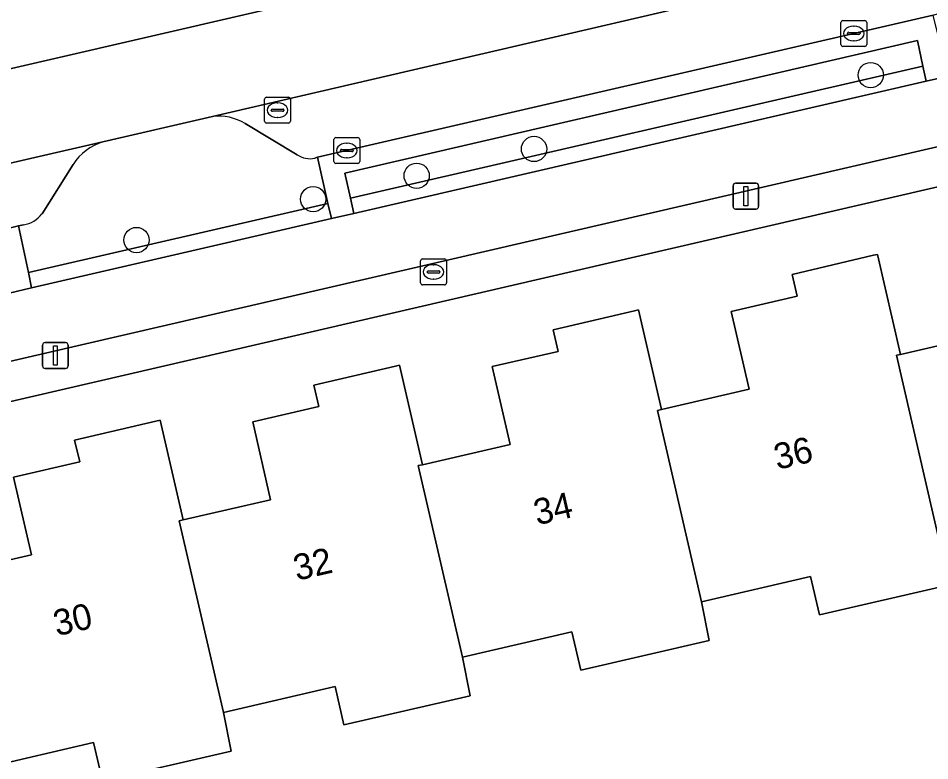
# Model space of a CAD drawing. Extents: x 156412 to 157779, y 382335 to 383768.
# Drawn here: x 156851.95 to 156887.22, y 382924.67 to 382953.4 of the extents above; entities that cross this region are included whole.
import ezdxf

# ---------------------------------------------------------------- set-up
doc = ezdxf.new("R2010")
doc.units = 0
for name, color, linetype in [('IMGEO_Berm_groen', 7, 'Continuous'), ('IMGEO_Boom', 7, 'Continuous'), ('IMGEO_Brandkraan', 7, 'Continuous'), ('IMGEO_Erf', 7, 'Continuous'), ('IMGEO_Fietspad_gesloten', 7, 'Continuous'), ('IMGEO_Groenvoorziening', 7, 'Continuous'), ('IMGEO_Haag', 7, 'Continuous'), ('IMGEO_Kolk', 7, 'Continuous'), ('IMGEO_Lichtmast', 7, 'Continuous'), ('IMGEO_Pand', 7, 'Continuous'), ('IMGEO_Pand_nummerreeks', 7, 'Continuous'), ('IMGEO_Parkeervlak_open', 7, 'Continuous'), ('IMGEO_Rijbaan_regionaal_gesloten', 7, 'Continuous'), ('IMGEO_Rioolput', 7, 'Continuous'), ('IMGEO_Voetpad_open', 7, 'Continuous')]:
    doc.layers.add(name, color=color, linetype=linetype)

msp = doc.modelspace()

# ---------------------------------------------------------------- linework, layer by layer
at = {"layer": 'IMGEO_Berm_groen'}
msp.add_lwpolyline([(156886.962, 382951.547), (156886.748, 382952.533), (156864.584, 382947.403), (156864.803, 382946.432)], close=True, dxfattribs=at)
for points in [[(156859.463, 382949.6), (156855.226, 382948.615)], [(156862.74, 382948.115), (156860.735, 382949.326)], [(156852.15, 382945.404), (156851.962, 382945.371), (156852.339, 382943.555), (156863.935, 382946.232), (156863.529, 382948.017)], [(156854.068, 382947.742), (156852.867, 382945.83)], [(156863.529, 382948.017), (156863.421, 382947.98)]]:
    msp.add_lwpolyline(points, dxfattribs=at)
for centre, radius, start, end in [((156859.679, 382947.512), 2.099, 59.7879, 95.8996), ((156855.857, 382946.574), 2.137, 107.174, 146.8503), ((156863.237, 382948.836), 0.875, 235.421, 282.1534), ((156851.957, 382946.545), 1.157, 279.5863, 321.8464)]:
    msp.add_arc(centre, radius, start, end, dxfattribs=at)
at = {"layer": 'IMGEO_Boom'}
for centre in [(156884.939, 382951.198), (156871.909, 382948.34), (156867.367, 382947.304), (156863.362, 382946.399), (156856.524, 382944.817)]:
    msp.add_circle(centre, 0.489, dxfattribs=at)
at = {"layer": 'IMGEO_Brandkraan'}
for p, q in [((156867.52, 382943.158), (156867.52, 382944.01)), ((156867.595, 382944.084), (156868.447, 382944.084)), ((156868.008, 382943.864), (156868.033, 382943.864)), ((156868.521, 382944.01), (156868.521, 382943.158)), ((156867.779, 382943.578), (156867.779, 382943.59)), ((156868.217, 382943.541), (156867.819, 382943.541)), ((156867.822, 382943.627), (156868.22, 382943.627)), ((156868.263, 382943.59), (156868.263, 382943.578)), ((156868.031, 382943.304), (156868.006, 382943.304)), ((156868.447, 382943.084), (156867.595, 382943.084))]:
    msp.add_line(p, q, dxfattribs=at)
for points in [[(156867.52, 382943.158), (156867.52, 382944.01)], [(156867.595, 382944.084), (156868.447, 382944.084)], [(156868.521, 382944.01), (156868.521, 382943.158)], [(156868.447, 382943.084), (156867.595, 382943.084)]]:
    msp.add_lwpolyline(points, dxfattribs=at)
for centre, radius, start, end in [((156867.597, 382944.008), 0.0765, 91.552, 178.448), ((156867.597, 382944.008), 0.0765, 91.552, 178.448), ((156868.445, 382944.008), 0.0765, 1.552, 88.448), ((156868.445, 382944.008), 0.0765, 1.552, 88.448), ((156867.819, 382943.587), 0.0403, 85.8775, 175.7526), ((156867.816, 382943.577), 0.0366, 178.938, 274.7102), ((156868.22, 382943.584), 0.043, 264.8664, 352.4533), ((156868.224, 382943.589), 0.0386, 1.7309, 96.639), ((156867.597, 382943.16), 0.0765, 181.552, 268.448), ((156867.597, 382943.16), 0.0765, 181.552, 268.448), ((156868.445, 382943.16), 0.0765, 271.552, 358.448), ((156868.445, 382943.16), 0.0765, 271.552, 358.448)]:
    msp.add_arc(centre, radius, start, end, dxfattribs=at)
for centre, major_axis, ratio, start_param, end_param in [((156868.007, 382943.584), (-0.387, 0.002), 0.722429, 4.712389, 7.853982), ((156868.032, 382943.584), (-0.39, 0.002), 0.717154, 1.570796, 4.712389)]:
    msp.add_ellipse(centre, major_axis=major_axis, ratio=ratio, start_param=start_param, end_param=end_param, dxfattribs=at)
at = {"layer": 'IMGEO_Erf'}
for points in [[(156903.296, 382950.523), (156828.922, 382933.312)], [(156849.094, 382931.86), (156852.463, 382932.637), (156851.769, 382935.646), (156854.325, 382936.236), (156854.131, 382937.073), (156857.276, 382937.806), (156857.442, 382937.845), (156858.331, 382933.991), (156861.707, 382934.77), (156861.023, 382937.781), (156863.582, 382938.372), (156863.389, 382939.207), (156866.542, 382939.942), (156866.699, 382939.979), (156867.588, 382936.126), (156870.985, 382936.91), (156870.291, 382939.92), (156872.847, 382940.51), (156872.655, 382941.344), (156875.797, 382942.083), (156875.952, 382942.119), (156876.842, 382938.261), (156880.23, 382939.043), (156879.535, 382942.053), (156882.092, 382942.643), (156881.898, 382943.484), (156885.05, 382944.228), (156885.198, 382944.263), (156886.09, 382940.395), (156889.48, 382941.177)], [(156887.931, 382931.468), (156882.956, 382930.318), (156882.614, 382931.798), (156878.388, 382930.821), (156878.691, 382929.332), (156873.716, 382928.181), (156873.374, 382929.661), (156869.138, 382928.681), (156869.432, 382927.191), (156864.554, 382926.063), (156864.212, 382927.542), (156859.889, 382926.543), (156860.182, 382925.052), (156855.207, 382923.901), (156854.865, 382925.381), (156850.649, 382924.406)]]:
    msp.add_lwpolyline(points, dxfattribs=at)
at = {"layer": 'IMGEO_Fietspad_gesloten'}
msp.add_lwpolyline([(156674.773, 382899.258), (156767.182, 382920.602), (156826.292, 382934.262), (156902.955, 382951.999), (156911.251, 382953.909), (156913.318, 382954.385), (156939.803, 382960.484), (156939.156, 382962.984), (156887.943, 382951.159), (156887.089, 382950.962), (156864.935, 382945.847), (156864.068, 382945.647), (156859.834, 382944.669), (156852.462, 382942.964), (156851.598, 382942.764), (156830.312, 382937.841), (156829.479, 382937.648), (156815.976, 382934.507), (156815.173, 382934.345)], dxfattribs=at)
at = {"layer": 'IMGEO_Groenvoorziening'}
for points in [[(156887.089, 382950.962), (156886.962, 382951.547), (156864.803, 382946.432), (156864.935, 382945.847)], [(156859.834, 382944.669), (156864.068, 382945.647), (156863.935, 382946.232), (156852.339, 382943.555), (156852.462, 382942.964)]]:
    msp.add_lwpolyline(points, close=True, dxfattribs=at)
at = {"layer": 'IMGEO_Haag'}
for points in [[(156886.962, 382951.547), (156864.803, 382946.432), (156864.935, 382945.847), (156887.089, 382950.962)], [(156863.935, 382946.232), (156852.339, 382943.555), (156852.462, 382942.964), (156859.834, 382944.669), (156864.068, 382945.647)]]:
    msp.add_lwpolyline(points, close=True, dxfattribs=at)
at = {"layer": 'IMGEO_Kolk'}
for p, q in [((156883.784, 382952.382), (156883.784, 382953.234)), ((156883.859, 382953.308), (156884.711, 382953.308)), ((156884.272, 382953.088), (156884.297, 382953.088)), ((156884.785, 382953.234), (156884.785, 382952.382)), ((156884.043, 382952.802), (156884.043, 382952.814)), ((156884.481, 382952.765), (156884.083, 382952.765)), ((156884.086, 382952.851), (156884.484, 382952.851)), ((156884.527, 382952.814), (156884.527, 382952.802)), ((156884.711, 382952.308), (156883.859, 382952.308)), ((156884.295, 382952.528), (156884.27, 382952.528)), ((156864.24, 382948.779), (156865.092, 382948.779)), ((156864.165, 382947.853), (156864.165, 382948.705)), ((156864.653, 382948.559), (156864.678, 382948.559)), ((156865.166, 382948.705), (156865.166, 382947.853)), ((156864.424, 382948.273), (156864.424, 382948.285)), ((156864.862, 382948.236), (156864.464, 382948.236)), ((156864.467, 382948.322), (156864.865, 382948.322)), ((156864.908, 382948.285), (156864.908, 382948.273)), ((156865.092, 382947.779), (156864.24, 382947.779)), ((156864.676, 382947.999), (156864.651, 382947.999))]:
    msp.add_line(p, q, dxfattribs=at)
for points in [[(156883.784, 382952.382), (156883.784, 382953.234)], [(156883.859, 382953.308), (156884.711, 382953.308)], [(156884.785, 382953.234), (156884.785, 382952.382)], [(156884.711, 382952.308), (156883.859, 382952.308)], [(156864.24, 382948.779), (156865.092, 382948.779)], [(156864.165, 382947.853), (156864.165, 382948.705)], [(156865.166, 382948.705), (156865.166, 382947.853)], [(156865.092, 382947.779), (156864.24, 382947.779)]]:
    msp.add_lwpolyline(points, dxfattribs=at)
for centre, radius, start, end in [((156883.861, 382953.232), 0.0765, 91.552, 178.448), ((156883.861, 382953.232), 0.0765, 91.552, 178.448), ((156884.709, 382953.232), 0.0765, 1.552, 88.448), ((156884.709, 382953.232), 0.0765, 1.552, 88.448), ((156884.083, 382952.811), 0.0403, 85.8775, 175.7526), ((156884.08, 382952.801), 0.0366, 178.938, 274.7102), ((156884.484, 382952.808), 0.043, 264.8664, 352.4533), ((156884.488, 382952.813), 0.0386, 1.7309, 96.639), ((156883.861, 382952.384), 0.0765, 181.552, 268.448), ((156883.861, 382952.384), 0.0765, 181.552, 268.448), ((156884.709, 382952.384), 0.0765, 271.552, 358.448), ((156884.709, 382952.384), 0.0765, 271.552, 358.448), ((156864.242, 382948.703), 0.0765, 91.552, 178.448), ((156864.242, 382948.703), 0.0765, 91.552, 178.448), ((156865.09, 382948.703), 0.0765, 1.552, 88.448), ((156865.09, 382948.703), 0.0765, 1.552, 88.448), ((156864.464, 382948.282), 0.0403, 85.8775, 175.7526), ((156864.461, 382948.272), 0.0366, 178.938, 274.7102), ((156864.865, 382948.279), 0.043, 264.8664, 352.4533), ((156864.869, 382948.284), 0.0386, 1.7309, 96.639), ((156864.242, 382947.855), 0.0765, 181.552, 268.448), ((156864.242, 382947.855), 0.0765, 181.552, 268.448), ((156865.09, 382947.855), 0.0765, 271.552, 358.448), ((156865.09, 382947.855), 0.0765, 271.552, 358.448)]:
    msp.add_arc(centre, radius, start, end, dxfattribs=at)
for centre, major_axis, ratio, start_param, end_param in [((156884.271, 382952.808), (-0.387, 0.002), 0.722429, 4.712389, 7.853982), ((156884.296, 382952.808), (-0.39, 0.002), 0.717154, 1.570796, 4.712389), ((156864.652, 382948.279), (-0.387, 0.002), 0.722429, 4.712389, 7.853982), ((156864.677, 382948.279), (-0.39, 0.002), 0.717154, 1.570796, 4.712389)]:
    msp.add_ellipse(centre, major_axis=major_axis, ratio=ratio, start_param=start_param, end_param=end_param, dxfattribs=at)
at = {"layer": 'IMGEO_Lichtmast'}
for p, q in [((156879.71, 382947.017), (156880.5, 382947.017)), ((156880.5, 382947.017), (156879.71, 382947.017)), ((156879.61, 382946.117), (156879.61, 382946.917)), ((156879.61, 382946.917), (156879.61, 382946.117)), ((156880.6, 382946.917), (156880.6, 382946.117)), ((156880.6, 382946.117), (156880.6, 382946.917)), ((156880.5, 382946.017), (156879.71, 382946.017)), ((156879.71, 382946.017), (156880.5, 382946.017)), ((156852.889, 382939.95), (156852.889, 382940.75)), ((156852.889, 382940.75), (156852.889, 382939.95)), ((156852.989, 382940.85), (156853.779, 382940.85)), ((156853.779, 382940.85), (156852.989, 382940.85)), ((156853.879, 382940.75), (156853.879, 382939.95)), ((156853.879, 382939.95), (156853.879, 382940.75)), ((156853.779, 382939.85), (156852.989, 382939.85)), ((156852.989, 382939.85), (156853.779, 382939.85))]:
    msp.add_line(p, q, dxfattribs=at)
for points in [[(156880.03, 382946.892), (156880.18, 382946.892), (156880.18, 382946.142), (156880.03, 382946.142), (156880.03, 382946.892)], [(156853.309, 382940.725), (156853.459, 382940.725), (156853.459, 382939.975), (156853.309, 382939.975), (156853.309, 382940.725)]]:
    msp.add_lwpolyline(points, dxfattribs=at)
for centre, start, end in [((156879.71, 382946.917), 90, 180), ((156879.71, 382946.917), 90, 180), ((156880.5, 382946.917), 0, 90), ((156880.5, 382946.917), 360, 90), ((156879.71, 382946.117), 180, 270), ((156879.71, 382946.117), 180, 270), ((156880.5, 382946.117), 270, 0), ((156880.5, 382946.117), 270, 0), ((156852.989, 382940.75), 90, 180), ((156852.989, 382940.75), 90, 180), ((156853.779, 382940.75), 0, 90), ((156853.779, 382940.75), 360, 90), ((156852.989, 382939.95), 180, 270), ((156852.989, 382939.95), 180, 270), ((156853.779, 382939.95), 270, 0), ((156853.779, 382939.95), 270, 0)]:
    msp.add_arc(centre, 0.1, start, end, dxfattribs=at)
at = {"layer": 'IMGEO_Pand'}
for points in [[(156895.379, 382942.538), (156894.488, 382946.399), (156894.308, 382946.357), (156891.153, 382945.628), (156891.349, 382944.779), (156888.785, 382944.187), (156889.48, 382941.177), (156886.09, 382940.395), (156885.938, 382940.36), (156887.638, 382932.959), (156891.863, 382933.937), (156892.205, 382932.457), (156897.19, 382933.61), (156896.897, 382935.101), (156895.196, 382942.496)], [(156876.842, 382938.261), (156876.685, 382938.225), (156878.388, 382930.821), (156882.614, 382931.798), (156882.956, 382930.318), (156887.931, 382931.468), (156887.638, 382932.959), (156885.938, 382940.36), (156886.09, 382940.395), (156885.198, 382944.263), (156885.05, 382944.228), (156881.898, 382943.484), (156882.092, 382942.643), (156879.535, 382942.053), (156880.23, 382939.043)], [(156867.588, 382936.126), (156867.43, 382936.09), (156869.138, 382928.681), (156873.374, 382929.661), (156873.716, 382928.181), (156878.691, 382929.332), (156878.388, 382930.821), (156876.685, 382938.225), (156876.842, 382938.261), (156875.952, 382942.119), (156875.797, 382942.083), (156872.655, 382941.344), (156872.847, 382940.51), (156870.291, 382939.92), (156870.985, 382936.91)], [(156867.588, 382936.126), (156866.699, 382939.979), (156866.542, 382939.942), (156863.389, 382939.207), (156863.582, 382938.372), (156861.023, 382937.781), (156861.707, 382934.77), (156858.331, 382933.991), (156858.17, 382933.954), (156859.889, 382926.543), (156864.212, 382927.542), (156864.554, 382926.063), (156869.432, 382927.191), (156869.138, 382928.681), (156867.43, 382936.09)], [(156849.094, 382931.86), (156848.925, 382931.821), (156850.649, 382924.406), (156854.865, 382925.381), (156855.207, 382923.901), (156860.182, 382925.052), (156859.889, 382926.543), (156858.17, 382933.954), (156858.331, 382933.991), (156857.442, 382937.845), (156857.276, 382937.806), (156854.131, 382937.073), (156854.325, 382936.236), (156851.769, 382935.646), (156852.463, 382932.637)]]:
    msp.add_lwpolyline(points, close=True, dxfattribs=at)
at = {"layer": 'IMGEO_Parkeervlak_open'}
for points in [[(156890.458, 382956.801), (156859.463, 382949.6)], [(156863.421, 382947.98), (156863.529, 382948.017), (156887.359, 382953.518), (156887.565, 382953.583)], [(156860.735, 382949.326), (156862.74, 382948.115)], [(156855.226, 382948.615), (156824.808, 382941.614)], [(156852.867, 382945.83), (156854.068, 382947.742)], [(156828.775, 382940.011), (156828.946, 382940.054), (156845.143, 382943.683), (156851.962, 382945.371), (156852.15, 382945.404)]]:
    msp.add_lwpolyline(points, dxfattribs=at)
for centre, radius, start, end in [((156859.679, 382947.512), 2.099, 59.7879, 95.8996), ((156855.857, 382946.574), 2.137, 107.174, 146.8503), ((156863.237, 382948.836), 0.875, 235.421, 282.1534), ((156851.957, 382946.545), 1.157, 279.5863, 321.8464)]:
    msp.add_arc(centre, radius, start, end, dxfattribs=at)
at = {"layer": 'IMGEO_Rijbaan_regionaal_gesloten'}
msp.add_lwpolyline([(156816.196, 382943.116), (156816.29, 382943.135), (156830.232, 382946.499), (156903.004, 382963.32), (156939.797, 382971.848)], dxfattribs=at)
msp.add_lwpolyline([(156940.547, 382968.546), (156939.797, 382971.848), (156903.004, 382963.32), (156830.232, 382946.499), (156816.29, 382943.135), (156816.196, 382943.116), (156816.994, 382939.753), (156818.685, 382940.216), (156824.808, 382941.614), (156855.226, 382948.615), (156859.463, 382949.6), (156890.458, 382956.801), (156893.4, 382957.443), (156903.126, 382959.769)], close=True, dxfattribs=at)
at = {"layer": 'IMGEO_Rioolput'}
for p, q in [((156861.482, 382949.413), (156861.482, 382950.265)), ((156861.557, 382950.339), (156862.409, 382950.339)), ((156862.483, 382950.265), (156862.483, 382949.413)), ((156861.741, 382949.833), (156861.741, 382949.845)), ((156861.784, 382949.882), (156862.182, 382949.882)), ((156861.97, 382950.119), (156861.995, 382950.119)), ((156862.225, 382949.845), (156862.225, 382949.833)), ((156862.179, 382949.796), (156861.781, 382949.796)), ((156861.993, 382949.559), (156861.968, 382949.559)), ((156862.409, 382949.339), (156861.557, 382949.339))]:
    msp.add_line(p, q, dxfattribs=at)
for points in [[(156861.482, 382949.413), (156861.482, 382950.265)], [(156861.557, 382950.339), (156862.409, 382950.339)], [(156862.483, 382950.265), (156862.483, 382949.413)], [(156862.409, 382949.339), (156861.557, 382949.339)]]:
    msp.add_lwpolyline(points, dxfattribs=at)
for centre, radius, start, end in [((156861.559, 382950.263), 0.0765, 91.552, 178.448), ((156861.559, 382950.263), 0.0765, 91.552, 178.448), ((156862.407, 382950.263), 0.0765, 1.552, 88.448), ((156862.407, 382950.263), 0.0765, 1.552, 88.448), ((156861.781, 382949.842), 0.0403, 85.8775, 175.7526), ((156861.778, 382949.832), 0.0366, 178.938, 274.7102), ((156862.182, 382949.839), 0.043, 264.8664, 352.4533), ((156862.186, 382949.844), 0.0386, 1.7309, 96.639), ((156861.559, 382949.415), 0.0765, 181.552, 268.448), ((156861.559, 382949.415), 0.0765, 181.552, 268.448), ((156862.407, 382949.415), 0.0765, 271.552, 358.448), ((156862.407, 382949.415), 0.0765, 271.552, 358.448)]:
    msp.add_arc(centre, radius, start, end, dxfattribs=at)
for centre, major_axis, ratio, start_param, end_param in [((156861.969, 382949.839), (-0.387, 0.002), 0.722429, 4.712389, 7.853982), ((156861.994, 382949.839), (-0.39, 0.002), 0.717154, 1.570796, 4.712389)]:
    msp.add_ellipse(centre, major_axis=major_axis, ratio=ratio, start_param=start_param, end_param=end_param, dxfattribs=at)
at = {"layer": 'IMGEO_Voetpad_open'}
for points in [[(156903.296, 382950.523), (156904.698, 382950.847), (156910.458, 382952.176), (156911.592, 382952.432), (156911.251, 382953.909), (156902.955, 382951.999), (156826.292, 382934.262), (156767.182, 382920.602), (156674.773, 382899.258)], [(156673.213, 382897.345), (156682.265, 382899.418), (156684.12, 382899.829), (156774.309, 382920.694), (156774.651, 382920.773), (156774.992, 382920.852), (156776.018, 382921.089), (156779.301, 382921.834), (156780.385, 382922.087), (156781.069, 382922.247), (156806.375, 382928.091), (156824.938, 382932.403), (156827.589, 382932.999), (156827.978, 382933.083), (156828.922, 382933.312), (156903.296, 382950.523)]]:
    msp.add_lwpolyline(points, dxfattribs=at)
for points in [[(156887.089, 382950.962), (156887.943, 382951.159), (156887.799, 382951.74), (156887.359, 382953.518), (156863.529, 382948.017), (156863.935, 382946.232), (156864.068, 382945.647), (156864.935, 382945.847), (156864.803, 382946.432), (156864.584, 382947.403), (156886.748, 382952.533), (156886.962, 382951.547)], [(156828.946, 382940.054), (156829.346, 382938.248), (156829.479, 382937.648), (156830.312, 382937.841), (156830.187, 382938.442), (156829.971, 382939.479), (156851.273, 382944.329), (156851.475, 382943.356), (156851.598, 382942.764), (156852.462, 382942.964), (156852.339, 382943.555), (156851.962, 382945.371), (156845.143, 382943.683)]]:
    msp.add_lwpolyline(points, close=True, dxfattribs=at)

# ---------------------------------------------------------------- texts
at = {"layer": 'IMGEO_Pand_nummerreeks'}
for s, p in [('36', (156881.322, 382935.924)), ('34', (156872.026, 382933.778)), ('32', (156862.727, 382931.632)), ('30', (156853.437, 382929.488))]:
    msp.add_text(s, height=1, rotation=12.9947, dxfattribs=at).set_placement(p)

doc.saveas('drawing.dxf')
